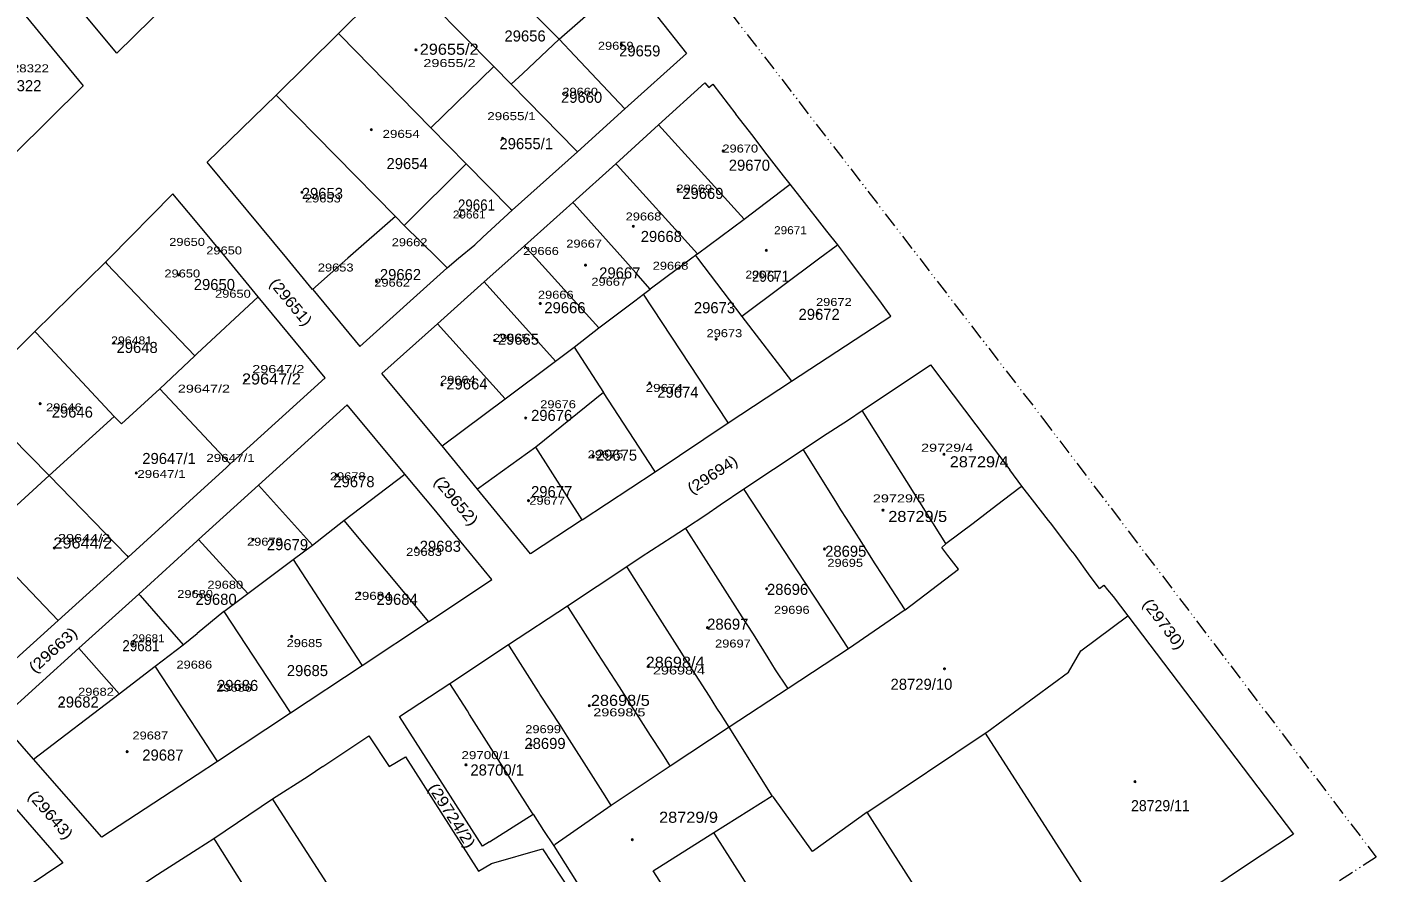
# Model space of a CAD drawing. Extents: x 650553 to 652508, y 239277 to 241647.
# Drawn here: x 652069.7 to 652508.1, y 240800.4 to 241075.2 of the extents above; entities that cross this region are included whole.
import ezdxf

# ---------------------------------------------------------------- set-up
doc = ezdxf.new("R2010")
doc.units = 0
doc.header["$PDMODE"] = 32
doc.header["$PDSIZE"] = 0.5
doc.linetypes.add('DASH_DOUBLE_DOT', pattern=[9.2, 5, -1.2, 0.3, -1.2, 0.3, -1.2])
for name, color, linetype in [('19', 7, 'Continuous'), ('20', 7, 'Continuous'), ('6', 7, 'Continuous')]:
    doc.layers.add(name, color=color, linetype=linetype)
for name, color, linetype, lineweight in [('3', 7, 'Continuous', 13), ('5', 7, 'Continuous', 13), ('52', 7, 'DASH_DOUBLE_DOT', 13)]:
    doc.layers.add(name, color=color, linetype=linetype, lineweight=lineweight)

msp = doc.modelspace()

# ---------------------------------------------------------------- linework, layer by layer
at = {"layer": '3'}
for p, q in [((652206.11, 240996.84), (652206.221, 240996.931)), ((652203.08, 240978.69), (652218.25, 240992.37)), ((652216.15, 240924.93), (652204.61, 240938.97)), ((652079.85, 240882.2), (652102.63, 240902.86)), ((652086.59, 240873.17), (652106.09, 240890.8)), ((652220.07, 240810.21), (652234.25, 240819.2))]:
    msp.add_line(p, q, dxfattribs=at)
for points in [[(652121.57, 241088.99), (652098.88, 241066.75), (652058.02, 241115.72)], [(652150.66, 241053.06), (652170.97, 241073.05), (652191.12, 241093.11), (652206.29, 241107.91)], [(652067.78, 241080.53), (652087.98, 241056.04), (652065.72, 241034.07)], [(652274.57, 241078.57), (652284.02, 241066.57), (652263.96, 241048.58)], [(652274.93, 241043.39), (652290.03, 241057.08), (652291.33, 241055.58), (652292.57, 241056.58), (652300.05, 241046.84)], [(652154.15, 241000), (652128.26, 241031.3), (652150.66, 241053.06)], [(652227.39, 241015.62), (652248.57, 241034.61), (652263.96, 241048.58)], [(652218.25, 240992.37), (652226.91, 241000), (652231.42, 241004.03), (652247.08, 241018.16), (652261.04, 241030.77), (652274.93, 241043.39)], [(652317.76, 241024.16), (652315.59, 241026.8), (652309.49, 241034.62), (652305.74, 241039.72), (652300.05, 241046.84)], [(652333.19, 241004.34), (652329.66, 241008.86), (652320.85, 241020.11), (652317.76, 241024.16)], [(652125, 241011.53), (652117.11, 241020.94), (652096.4, 240999.97)], [(652206.221, 240996.931), (652209.97, 241000), (652215.29, 241004.34), (652217.83, 241006.87), (652227.39, 241015.62)], [(652144.85, 240987.47), (652134.51, 241000), (652125, 241011.53)], [(652347.41, 240985.41), (652336.48, 241000), (652334.87, 241002.16), (652333.19, 241004.34)], [(652029.57, 240933.88), (652051.36, 240955.22), (652072.28, 240976.15), (652095.19, 240998.75), (652096.4, 240999.97)], [(652162.59, 240989.8), (652162.506, 240989.901), (652154.15, 241000)], [(652162.59, 240989.8), (652177.91, 240971.27), (652206.11, 240996.84)], [(652137.56, 240934.79), (652166.66, 240961.08), (652144.85, 240987.47)], [(652318.13, 240959.99), (652350.43, 240981.2), (652347.41, 240985.41)], [(652204.61, 240938.97), (652185.06, 240962.58), (652203.08, 240978.69)], [(652341.17, 240950.54), (652363.31, 240965.33), (652389.11, 240931.24)], [(652250.19, 240914.97), (652273.9, 240930.59), (652297.62, 240946.5), (652318.13, 240959.99)], [(652192.52, 240929.79), (652173.77, 240952.34), (652144.91, 240926.17)], [(652321.92, 240937.85), (652328.24, 240942.08), (652336.66, 240947.51), (652341.17, 240950.54)], [(652134.46, 240931.87), (652135.78, 240933.12), (652137.56, 240934.79)], [(652283.74, 240912.25), (652290.34, 240916.6), (652295.03, 240919.84), (652302.69, 240924.99), (652321.92, 240937.85)], [(652102.63, 240902.86), (652125, 240923.25), (652134.46, 240931.87)], [(652205.83, 240913.8), (652202.57, 240917.8), (652192.52, 240929.79)], [(652418.26, 240892.57), (652415.29, 240896.67), (652410.11, 240903.78), (652409.59, 240904.4), (652408.9, 240905.32), (652402.74, 240913.46), (652402.33, 240913.92), (652401.72, 240914.71), (652396.54, 240921.47), (652393.04, 240925.92), (652389.11, 240931.24)], [(652106.09, 240890.8), (652125, 240908.13), (652125.45, 240908.55), (652144.91, 240926.17)], [(652250.19, 240914.97), (652233.37, 240903.86), (652216.15, 240924.93)], [(652200.15, 240881.76), (652220.79, 240895.55), (652205.83, 240913.8)], [(652264.61, 240899.73), (652269.32, 240902.87), (652279.43, 240909.42), (652283.74, 240912.25)], [(652207.11, 240861.74), (652226.22, 240874.38), (652245.39, 240886.97), (652264.61, 240899.73)], [(652418.26, 240892.57), (652419.72, 240893.69), (652420.91, 240892.2)], [(652420.91, 240892.2), (652422.68, 240889.97), (652427.45, 240883.75)], [(652038.48, 240875.31), (652053.43, 240858.34), (652079.85, 240882.2)], [(652200.15, 240881.76), (652178.65, 240867.46), (652155.37, 240852.09), (652131.67, 240836.37), (652125, 240832.01)], [(652427.45, 240883.75), (652481.35, 240812.75), (652466.09, 240802.6)], [(652071.8, 240837.17), (652060.65, 240849.83), (652086.59, 240873.17)], [(652220.07, 240810.21), (652217.7, 240808.83), (652190.82, 240850.95), (652207.11, 240861.74)], [(652165.85, 240834.73), (652180.86, 240844.67), (652187.39, 240834.77), (652192.686, 240837.837), (652216.49, 240800.66)], [(652029.04, 240821.24), (652049.7, 240839.74), (652081.4, 240803.43), (652058.39, 240788.05)], [(652125, 240832.01), (652094.02, 240811.78), (652071.8, 240837.17)], [(652165.85, 240834.73), (652161.09, 240831.51), (652149.53, 240824.07), (652130.48, 240811.26)], [(652234.25, 240819.2), (652237.6, 240813.95), (652240.89, 240808.97), (652253.77, 240788.47)], [(652130.48, 240811.26), (652125, 240807.76), (652110.91, 240798.75), (652092.01, 240785.99), (652073.09, 240773.31), (652053.84, 240760.57)], [(652216.49, 240800.66), (652220.68, 240803.17), (652237.25, 240807.92), (652256.07, 240779.29)], [(652466.09, 240802.6), (652453.76, 240794.42), (652425.84, 240775.91), (652387.13, 240750.57)]]:
    msp.add_lwpolyline(points, dxfattribs=at)
at = {"layer": '5'}
for p, q in [((652221.38, 241062.42), (652227.01, 241056.59)), ((652274.93, 241043.39), (652302.78, 241012.74)), ((652212.47, 241030.71), (652192.24, 241010.64)), ((652189.5, 241013.61), (652174.01, 241000)), ((652287.63, 241001.45), (652302.78, 241012.74)), ((652162.506, 240989.901), (652174.01, 241000)), ((652206.221, 240996.931), (652203.09, 241000)), ((652235.08, 241000), (652255.6, 240977.39)), ((652263.36, 241000), (652267.56, 240995.31)), ((652285.75, 241000), (652272.29, 240990.01)), ((652286.93, 241000.88), (652287.6, 241000)), ((652327.39, 241000), (652302.05, 240981.04)), ((652241.5, 240966.59), (652218.25, 240992.37)), ((652144.85, 240987.47), (652125, 240968.99)), ((652203.08, 240978.69), (652225.13, 240954.27)), ((652368.38, 240907.21), (652341.17, 240950.54)), ((652250.19, 240914.97), (652235.08, 240938.55)), ((652172.73, 240914.74), (652200.15, 240881.76)), ((652054.4, 240908.79), (652079.85, 240882.2)), ((652133.73, 240885.1), (652141.47, 240890.96)), ((652133.73, 240885.1), (652125, 240878)), ((652086.59, 240873.17), (652099.66, 240858.32)), ((652125, 240846.52), (652111.34, 240867.33)), ((652297.95, 240847.5), (652295.29, 240851.63)), ((652387.13, 240750.57), (652342.803, 240819.836)), ((652282.14, 240787.08), (652273.23, 240800.78))]:
    msp.add_line(p, q, dxfattribs=at)
for points in [[(652206.29, 241107.91), (652226.68, 241087.43), (652242.7, 241071.24), (652247.71, 241065.85), (652263.96, 241048.58)], [(652191.12, 241093.11), (652191.613, 241092.61), (652221.38, 241062.42), (652200.98, 241042.45)], [(652227.01, 241056.59), (652230.87, 241060.14), (652242.7, 241071.24), (652264.91, 241090.8)], [(652170.97, 241073.05), (652171.46, 241072.55), (652200.98, 241042.45), (652212.47, 241030.71)], [(652227.01, 241056.59), (652248.08, 241035.11), (652248.57, 241034.61)], [(652150.66, 241053.06), (652189.5, 241013.61), (652192.24, 241010.64), (652203.09, 241000)], [(652212.47, 241030.71), (652226.896, 241016.12), (652227.39, 241015.62)], [(652261.04, 241030.77), (652261.493, 241030.27), (652287.63, 241001.45)], [(652302.78, 241012.74), (652317.26, 241023.779), (652317.76, 241024.16)], [(652247.08, 241018.16), (652247.528, 241017.66), (652263.36, 241000)], [(652231.42, 241004.03), (652231.874, 241003.53), (652235.08, 241000)], [(652333.19, 241004.34), (652332.69, 241003.966), (652327.39, 241000)], [(652287.63, 241001.45), (652286.93, 241000.88), (652285.75, 241000)], [(652287.6, 241000), (652302.05, 240981.04), (652318.13, 240959.99)], [(652095.19, 240998.75), (652095.668, 240998.25), (652124.28, 240968.32)], [(652270.06, 240988.32), (652272.29, 240990.01), (652267.56, 240995.31)], [(652247.56, 240971.15), (652255.6, 240977.39), (652267.21, 240986.2), (652270.06, 240988.32)], [(652297.62, 240946.5), (652297.29, 240947), (652270.06, 240988.32)], [(652072.28, 240976.15), (652072.747, 240975.65), (652098.09, 240948.54)], [(652112.85, 240957.53), (652124.28, 240968.32), (652125, 240968.99)], [(652204.61, 240938.97), (652225.13, 240954.27), (652241.5, 240966.59), (652247.56, 240971.15), (652257.12, 240956.35), (652235.08, 240938.55), (652216.15, 240924.93)], [(652098.09, 240948.54), (652100.43, 240946.18), (652112.85, 240957.53)], [(652112.85, 240957.53), (652135.31, 240933.62), (652135.78, 240933.12)], [(652273.9, 240930.59), (652273.574, 240931.09), (652257.12, 240956.35)], [(652051.36, 240955.22), (652051.853, 240954.72), (652076.91, 240929.32)], [(652054.4, 240908.79), (652076.91, 240929.32), (652098.09, 240948.54)], [(652332.9, 240920.42), (652322.235, 240937.35), (652321.92, 240937.85)], [(652076.91, 240929.32), (652102.144, 240903.36), (652102.63, 240902.86)], [(652162.55, 240906.7), (652172.73, 240914.74), (652192.52, 240929.79)], [(652125.45, 240908.55), (652141.47, 240890.96), (652156.21, 240902.03), (652162.55, 240906.7), (652144.91, 240926.17)], [(652322.36, 240894.85), (652303.016, 240924.49), (652302.69, 240924.99)], [(652389.81, 240923.49), (652392.54, 240925.544), (652393.04, 240925.92)], [(652355.16, 240885.65), (652347.82, 240896.81), (652345.16, 240900.91), (652340.99, 240907.53), (652336, 240915.34), (652334.23, 240918.15), (652332.9, 240920.42)], [(652368.38, 240907.21), (652377.23, 240913.81), (652384.82, 240919.73), (652389.81, 240923.49)], [(652292.02, 240899.2), (652284.057, 240911.75), (652283.74, 240912.25)], [(652355.16, 240885.65), (652372.45, 240898.88), (652370.13, 240901.81), (652368.93, 240903.39)], [(652368.93, 240903.39), (652367, 240906), (652368.31, 240907.16), (652368.38, 240907.21)], [(652156.21, 240902.03), (652178.325, 240867.96), (652178.65, 240867.46)], [(652274.74, 240883.88), (652264.93, 240899.23), (652264.61, 240899.73)], [(652317.13, 240860.06), (652316.792, 240860.56), (652312.97, 240866.22), (652310.64, 240870.04), (652305.79, 240877.8), (652303.78, 240880.89), (652302.94, 240882.26), (652294.33, 240895.63), (652292.02, 240899.2)], [(652336.72, 240873.01), (652336.393, 240873.51), (652326.36, 240888.87), (652322.36, 240894.85)], [(652106.09, 240890.8), (652106.527, 240890.3), (652120.5, 240874.33)], [(652255.23, 240871.45), (652245.707, 240886.47), (652245.39, 240886.97)], [(652355.16, 240885.65), (652336.72, 240873.01), (652317.13, 240860.06), (652297.95, 240847.5), (652278.79, 240834.8), (652259.55, 240822.07)], [(652133.73, 240885.1), (652155.042, 240852.59), (652155.37, 240852.09)], [(652295.29, 240851.63), (652293.9, 240853.66), (652291.49, 240857.57), (652283.65, 240869.9), (652281.81, 240872.8), (652274.74, 240883.88)], [(652381.13, 240845.574), (652381.63, 240845.939), (652408.241, 240865.366), (652412.185, 240872.322), (652427.45, 240883.75)], [(652071.8, 240837.17), (652099.66, 240858.32), (652111.34, 240867.33), (652120.5, 240874.33), (652125, 240878)], [(652235.91, 240859.05), (652226.536, 240873.88), (652226.22, 240874.38)], [(652276.11, 240839.07), (652272.34, 240844.79), (652262.31, 240860.59), (652255.23, 240871.45)], [(652234.25, 240819.2), (652233.93, 240819.7), (652213.53, 240851.61), (652212.83, 240852.79), (652207.11, 240861.74)], [(652256.89, 240826.4), (652253.01, 240832.34), (652245.21, 240844.61), (652243.06, 240848.04), (652236.34, 240858.26), (652235.91, 240859.05)], [(652131.67, 240836.37), (652131.341, 240836.87), (652125, 240846.52)], [(652273.23, 240800.78), (652292.972, 240813.264), (652311.91, 240825.24), (652297.95, 240847.5)], [(652342.803, 240819.836), (652343.303, 240820.172), (652381.13, 240845.574)], [(652381.13, 240845.574), (652425.519, 240776.41), (652425.84, 240775.91)], [(652278.79, 240834.8), (652278.476, 240835.3), (652276.11, 240839.07)], [(652149.53, 240824.07), (652149.852, 240823.57), (652171.52, 240789.92), (652174.3, 240785.49), (652184.49, 240769.61), (652196.75, 240749.99)], [(652259.55, 240822.07), (652259.243, 240822.57), (652256.89, 240826.4)], [(652342.803, 240819.836), (652324.969, 240807.106), (652312.27, 240824.74), (652311.91, 240825.24)], [(652259.55, 240822.07), (652241.39, 240809.321), (652240.89, 240808.97)], [(652130.48, 240811.26), (652130.794, 240810.76), (652140.3, 240795.6), (652144.73, 240788.82), (652151.66, 240778.03), (652162.65, 240760.59), (652169.47, 240750)], [(652349.23, 240724.96), (652348.911, 240725.46), (652293.291, 240812.764), (652292.972, 240813.264)]]:
    msp.add_lwpolyline(points, dxfattribs=at)
at = {"layer": '52'}
for points in [[(651848.117, 241638.653), (651850.85, 241640.826), (651854.855, 241643.843), (651859.061, 241646.967), (651862.077, 241642.993), (651865.187, 241639.299), (651868.69, 241635.11), (651876.454, 241625.813), (651886.134, 241613.883), (651968.083, 241508.86), (652062.325, 241387.051), (652163.19, 241255.731), (652270.107, 241116.584), (652399.768, 240948.012), (652508.14, 240805.294)], [(652508.14, 240805.294), (652415.96, 240744.924), (652255.621, 240638.986), (652125.045, 240552.683)]]:
    msp.add_lwpolyline(points, dxfattribs=at)
at = {"layer": '6'}
for p in [(652262.852, 241069.69), (652196.117, 241067.78), (652245.238, 241052.925), (652181.637, 241041.845), (652224.291, 241039.02), (652295.956, 241034.91), (652159.067, 241021.48), (652281.298, 241022.42), (652210.434, 241013.82), (652266.784, 241010.39), (652310.019, 241002.6), (652251.226, 240997.775), (652119.035, 240994.63), (652183.328, 240992.44), (652236.515, 240985.31), (652326.646, 240982.165), (652221.68, 240973.32), (652293.683, 240973.69), (652098.021, 240972.465), (652140.785, 240960.295), (652204.589, 240958.83), (652272.098, 240959.455), (652073.99, 240952.735), (652231.803, 240948.04), (652253.765, 240935.66), (652367.717, 240936.27), (652105.248, 240930.195), (652170.385, 240929.52), (652232.694, 240921.205), (652347.905, 240918.095), (652143.163, 240908.565), (652078.556, 240905.76), (652196.296, 240905.775), (652328.884, 240905.43), (652123.911, 240891.44), (652177.845, 240891.1), (652310.122, 240892.525), (652155.709, 240877.06), (652290.868, 240879.875), (652104.213, 240874.56), (652271.642, 240867.265), (652367.892, 240866.513), (652132.686, 240860.735), (652081.048, 240855.17), (652252.481, 240854.52), (652233.479, 240841.675), (652102.259, 240839.555), (652212.392, 240835.285), (652429.809, 240829.83), (652266.444, 240810.905)]:
    msp.add_point(p, dxfattribs=at)

# ---------------------------------------------------------------- texts
at = {"layer": '19'}
for s, p in [('29656', (652224.891, 241070.501)), ('29659', (652262.149, 241065.652)), ('28322', (652061.011, 241054.336)), ('29660', (652243.249, 241050.565)), ('29655/1', (652223.269, 241035.479)), ('29654', (652186.553, 241029.012)), ('29670', (652297.787, 241028.473)), ('29653', (652159.015, 241019.313)), ('29669', (652282.668, 241019.313)), ('29668', (652269.168, 241005.304)), ('29662', (652184.393, 240992.911)), ('29667', (652255.669, 240993.449)), ('29650', (652123.917, 240989.677)), ('29666', (652237.851, 240982.134)), ('29673', (652286.447, 240982.134)), ('29672', (652320.465, 240979.979)), ('29665', (652222.731, 240971.896)), ('29648', (652098.81, 240969.201)), ('29664', (652205.992, 240957.348)), ('29674', (652274.568, 240954.654)), ('29646', (652077.751, 240948.187)), ('29676', (652233.532, 240947.111)), ('29647/1', (652107.178, 240933.101)), ('29675', (652254.59, 240934.179)), ('29678', (652169.273, 240925.557)), ('29677', (652233.532, 240922.325)), ('29679', (652147.676, 240905.082)), ('29683', (652197.353, 240904.543)), ('28695', (652329.104, 240902.927)), ('28696', (652310.204, 240890.534)), ('29680', (652124.457, 240887.3)), ('29684', (652183.314, 240887.3)), ('28697', (652290.765, 240879.218)), ('29685', (652154.155, 240864.131)), ('28729/10', (652350.365, 240859.67)), ('29686', (652131.477, 240859.281)), ('29682', (652079.64, 240853.893)), ('28699', (652231.369, 240840.423)), ('29687', (652107.179, 240836.651)), ('28700/1', (652213.821, 240831.802))]:
    msp.add_text(s, height=3.6, dxfattribs=at).set_placement(p)
for s, width, p in [('29655/2', 1.1, (652197.351, 241066.192)), ('29661', 0.9, (652209.771, 241015.541)), ('29671', 0.9, (652305.346, 240992.372)), ('29647/2', 1.1, (652139.575, 240958.964)), ('28729/4', 1.1, (652369.6, 240932.023)), ('28729/5', 1.1, (652349.621, 240914.242)), ('29644/2', 1.1, (652078.289, 240905.62)), ('29681', 0.9, (652100.699, 240872.213)), ('28698/4', 1.1, (652270.787, 240866.825)), ('28698/5', 1.1, (652252.968, 240854.432)), ('28729/11', 0.95, (652428.529, 240820.195)), ('28729/9', 1.1, (652275.137, 240816.418))]:
    msp.add_text(s, height=3.6, dxfattribs=dict(at, width=width)).set_placement(p)
for s, rotation, width, p in [('(29651)', 309.572, 1.1, (652148.29, 240991.711)), ('(29694)', 33.389, 1.1, (652285.828, 240923.17)), ('(29652)', 309.97, 1.15, (652201.71, 240927.318)), ('(29730)', 307.204, 1.15, (652432.057, 240887.586)), ('(29663)', 42.159, 1.15, (652072.273, 240864.888)), ('(29724/2)', 302.438, 1.15, (652199.946, 240827.813)), ('(29643)', 311.122, 1.15, (652069.773, 240825.062))]:
    msp.add_text(s, height=3.6, rotation=rotation, dxfattribs=dict(at, width=width)).set_placement(p)
at = {"layer": '20'}
for s, width, p in [('29659', 1.2, (652255.244, 241067.809)), ('28322', 1.25, (652064.758, 241060.478)), ('29655/2', 1.35, (652198.534, 241062.191)), ('29660', 1.2, (652243.688, 241052.862)), ('29655/1', 1.25, (652219.309, 241044.922)), ('29654', 1.25, (652185.263, 241039.156)), ('29670', 1.2, (652295.712, 241034.398)), ('29669', 1.2, (652280.769, 241021.367)), ('29653', 1.2, (652160.066, 241018.164)), ('29661', 1.1, (652208.113, 241012.944)), ('29668', 1.2, (652264.273, 241012.303)), ('29671', 1.1, (652312.513, 241007.833)), ('29650', 1.2, (652115.933, 241004.028)), ('29650', 1.2, (652127.975, 241001.259)), ('29662', 1.2, (652188.246, 241003.921)), ('29666', 1.2, (652230.951, 241001.088)), ('29667', 1.2, (652244.974, 241003.482)), ('29650', 1.2, (652114.364, 240993.758)), ('29653', 1.2, (652164.235, 240995.7)), ('29668', 1.2, (652273.064, 240996.283)), ('29671', 1.1, (652303.224, 240993.402)), ('29662', 1.2, (652182.572, 240990.781)), ('29667', 1.2, (652253.128, 240991.07)), ('29650', 1.2, (652130.83, 240987.168)), ('29666', 1.2, (652235.762, 240986.85)), ('29672', 1.2, (652326.137, 240984.499)), ('296481', 1.15, (652097.047, 240971.987)), ('29665', 1.2, (652221.117, 240972.814)), ('29673', 1.2, (652290.555, 240974.35)), ('29647/2', 1.35, (652142.907, 240962.673)), ('29664', 1.2, (652203.957, 240959.179)), ('29647/2', 1.35, (652118.726, 240956.305)), ('29674', 1.25, (652270.79, 240956.544)), ('29646', 1.2, (652075.909, 240950.222)), ('29676', 1.2, (652236.506, 240951.238)), ('29729/4', 1.35, (652360.272, 240937.096)), ('29647/1', 1.25, (652127.988, 240933.786)), ('29675', 1.2, (652251.922, 240934.94)), ('29647/1', 1.25, (652105.554, 240928.56)), ('29678', 1.2, (652168.157, 240927.818)), ('29677', 1.2, (652232.962, 240919.861)), ('29729/5', 1.35, (652344.605, 240920.627)), ('29644/2', 1.35, (652079.784, 240907.724)), ('29679', 1.2, (652141.219, 240906.537)), ('29683', 1.2, (652192.934, 240903.233)), ('29695', 1.2, (652329.826, 240899.666)), ('29680', 1.2, (652128.348, 240892.546)), ('29680', 1.2, (652118.539, 240889.527)), ('29684', 1.25, (652176.12, 240888.927)), ('29696', 1.2, (652312.462, 240884.381)), ('29681', 1.1, (652103.823, 240875.119)), ('29685', 1.2, (652154.084, 240873.559)), ('29697', 1.2, (652293.337, 240873.416)), ('29686', 1.2, (652118.292, 240866.568)), ('29698/4', 1.35, (652273.132, 240864.653)), ('29682', 1.2, (652086.327, 240857.737)), ('29686', 1.2, (652131.212, 240859.068)), ('29698/5', 1.35, (652253.74, 240851.045)), ('29687', 1.2, (652103.989, 240843.515)), ('29699', 1.2, (652231.647, 240845.57)), ('29700/1', 1.25, (652210.917, 240837.124))]:
    msp.add_text(s, height=2.6, dxfattribs=dict(at, width=width)).set_placement(p)

doc.saveas('drawing.dxf')
